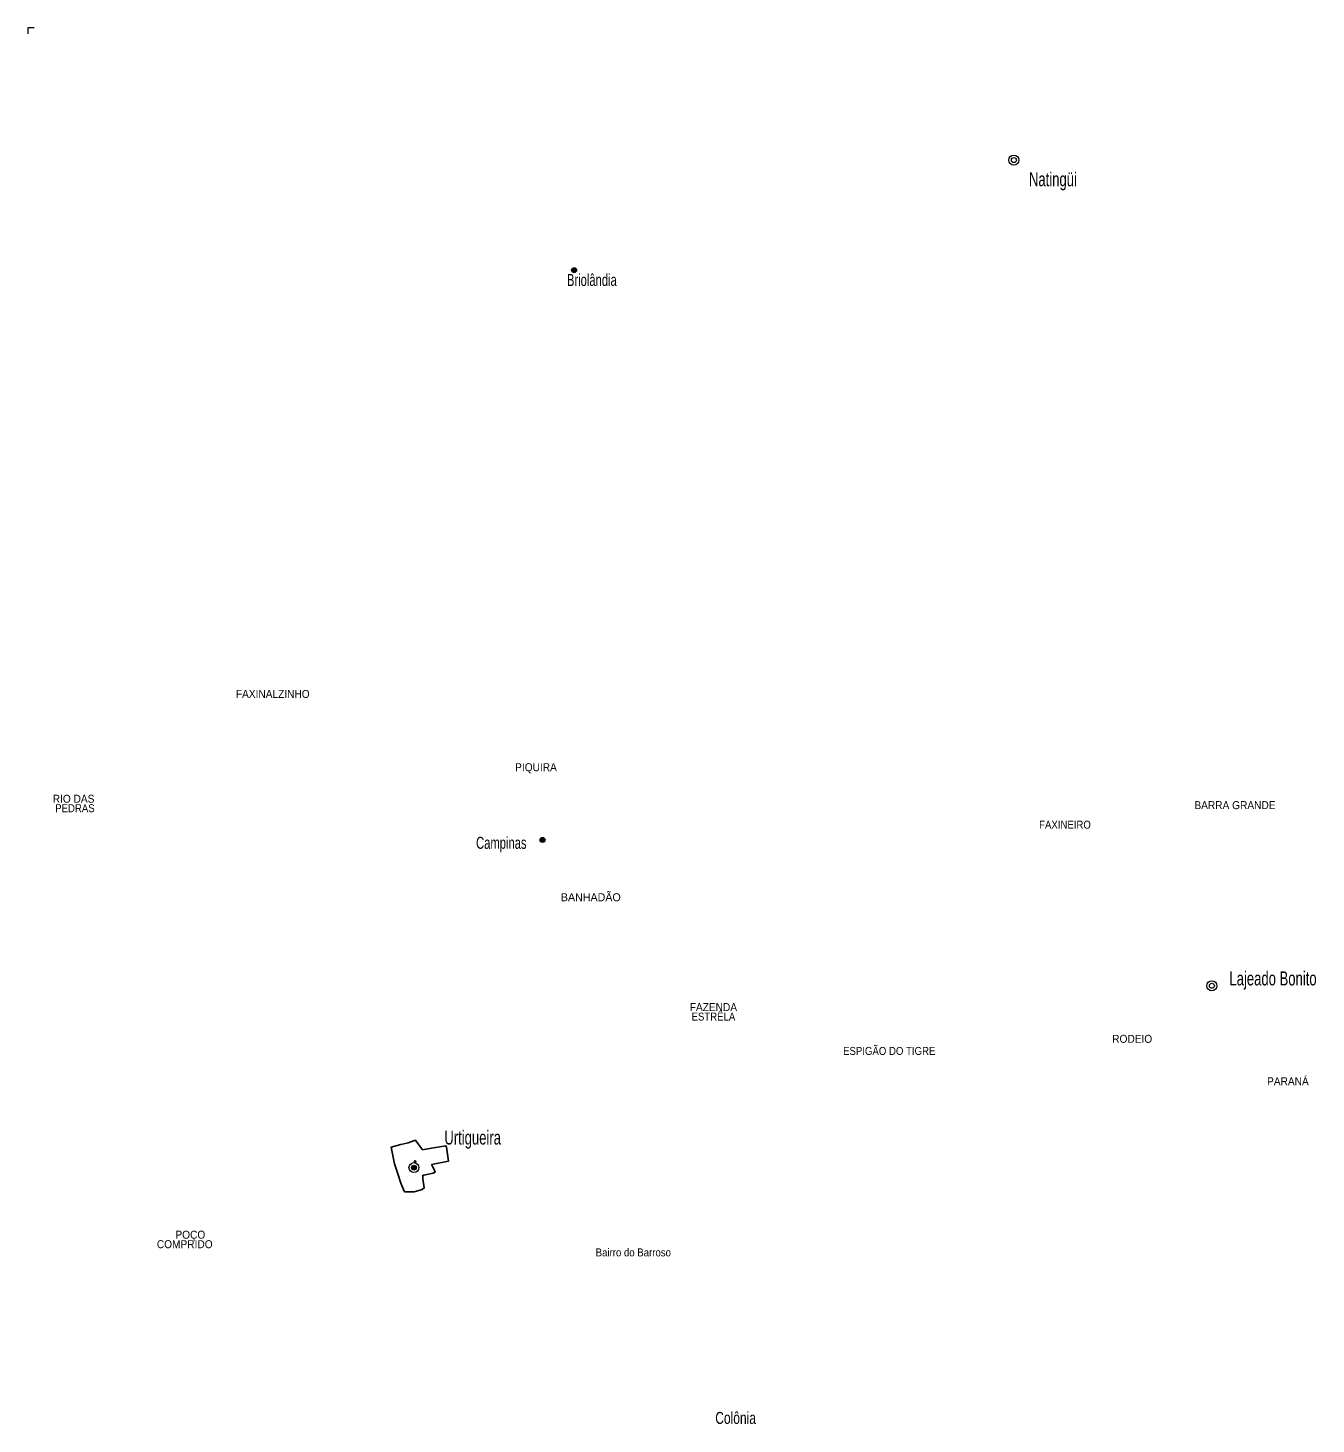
# Model space of a CAD drawing. Extents: x 500 to 550.9, y 7290.3 to 7345.7.
# Drawn here: x 499.99 to 525.82, y 7317.75 to 7345.74 of the extents above; entities that cross this region are included whole.
import ezdxf
from ezdxf.enums import TextEntityAlignment as Align

# ---------------------------------------------------------------- set-up
doc = ezdxf.new("R2010")
doc.units = 0
doc.header["$LTSCALE"] = 0.064
doc.header["$PDMODE"] = 32
doc.header["$PDSIZE"] = 0.032
for name, color, linetype, lineweight in [('41', 7, 'Continuous', 25), ('50', 7, 'Continuous', 13), ('51', 7, 'Continuous', 13), ('52', 7, 'Continuous', 13), ('63', 7, 'Continuous', 13)]:
    doc.layers.add(name, color=color, linetype=linetype, lineweight=lineweight)
doc.layers.add('56', color=7, linetype='Continuous')
doc.layers.add('61', color=7, linetype='Continuous')

msp = doc.modelspace()

# ---------------------------------------------------------------- hatches: boundary and pattern name
at = {"layer": '50'}
msp.add_hatch(color=256, dxfattribs=at).paths.add_polyline_path([(507.7804, 7322.8927, 1), (507.6804, 7322.8927, 1)])
at = {"layer": '52'}
for points in [[(510.99039, 7340.88426, 1), (510.89039, 7340.88426, 1)], [(510.35879, 7329.46256, 1), (510.25879, 7329.46256, 1)]]:
    msp.add_hatch(color=256, dxfattribs=at).paths.add_polyline_path(points)

# ---------------------------------------------------------------- linework, layer by layer
at = {"layer": '41'}
msp.add_line((507.7942, 7323.3976), (507.8983, 7323.2486), dxfattribs=at)
for points in [[(507.4669, 7323.3537), (507.584, 7323.3815), (507.6113, 7323.3905)], [(507.6113, 7323.3905), (507.7242, 7323.4275), (507.7592, 7323.4426), (507.7886, 7323.4056), (507.7942, 7323.3976)], [(507.4669, 7323.3537), (507.2706, 7323.3028), (507.3374, 7322.9713), (507.4042, 7322.771), (507.464, 7322.5799), (507.4806, 7322.5482)], [(507.8983, 7323.2486), (508.0809, 7323.2815), (508.326, 7323.3233), (508.3697, 7323.3309), (508.383, 7323.3005), (508.4226, 7323.0199), (508.0823, 7322.9529)], [(508.0823, 7322.9529), (508.1317, 7322.8657), (508.1578, 7322.803), (508.1161, 7322.7805), (507.9262, 7322.7398)], [(507.4806, 7322.5482), (507.5407, 7322.4102), (507.7333, 7322.4083)], [(507.9262, 7322.7398), (507.9058, 7322.738), (507.9104, 7322.6667), (507.938, 7322.4874), (507.938, 7322.4828), (507.8736, 7322.4484), (507.7333, 7322.4083)]]:
    msp.add_lwpolyline(points, dxfattribs=at)
msp.add_point((507.7548, 7323.0144), dxfattribs=at)
at = {"layer": '50'}
for radius in [0.1, 0.05]:
    msp.add_circle((507.7304, 7322.8927), radius, dxfattribs=at)
at = {"layer": '51'}
for centre, radius in [((519.7597, 7343.09234), 0.1), ((519.7597, 7343.09234), 0.05), ((523.7302, 7326.53894), 0.1), ((523.7302, 7326.53894), 0.05)]:
    msp.add_circle(centre, radius, dxfattribs=at)
at = {"layer": '52'}
for centre in [(510.94039, 7340.88426), (510.30879, 7329.46256)]:
    msp.add_circle(centre, 0.05, dxfattribs=at)
at = {"layer": '63'}
msp.add_lwpolyline([(500.1121, 7345.7419), (499.9889, 7345.7419), (499.9889, 7345.6205)], dxfattribs=at)

# ---------------------------------------------------------------- texts
at = {"layer": '56'}
for s, width, p in [('FAXINALZINHO', 0.95, (504.89865, 7332.3095)), ('PIQUIRA', 0.95, (510.17745, 7330.8404)), ('RIO DAS', 0.95, (500.9043, 7330.2085)), (' PEDRAS', 0.9, (500.9043, 7330.0185)), ('BARRA GRANDE', 0.95, (524.1937, 7330.0799)), ('FAXINEIRO', 0.9, (520.78545, 7329.6883)), ('FAZENDA', 0.95, (513.73505, 7326.031)), ('ESTRÊLA', 0.9, (513.73505, 7325.841)), ('ESPIGÃO DO TIGRE', 0.9, (517.26125, 7325.1526)), ('RODEIO', 0.95, (522.13315, 7325.3951)), ('PARANÁ', 0.95, (525.25505, 7324.5431)), ('COMPRIDO', 0.95, (503.1333, 7321.278)), ('    POÇO', 0.95, (503.1333, 7321.468))]:
    msp.add_text(s, height=0.16, dxfattribs=dict(at, width=width)).set_placement(p, align=Align.CENTER)
msp.add_text('BANHADÃO', height=0.16, dxfattribs=at).set_placement((511.2765, 7328.2335), align=Align.CENTER)
at = {"layer": '61'}
for s, height, width, p in [('Natingüi', 0.28, 0.7, (520.0629, 7342.5685)), ('Briolândia', 0.24, 0.7, (510.7982, 7340.5685)), ('Lajeado Bonito', 0.28, 0.7, (524.0825, 7326.546)), ('Urtigueira', 0.28, 0.7, (508.3394, 7323.3559)), ('Bairro do Barroso', 0.16, 0.9, (511.3744, 7321.1132))]:
    msp.add_text(s, height=height, dxfattribs=dict(at, width=width)).set_placement(p)
for s, width, p in [('Campinas', 0.7, (509.9874, 7329.2845)), ('         Colônia     ', 0.75, (514.9227, 7317.755))]:
    msp.add_text(s, height=0.24, dxfattribs=dict(at, width=width)).set_placement(p, align=Align.RIGHT)

doc.saveas('drawing.dxf')
